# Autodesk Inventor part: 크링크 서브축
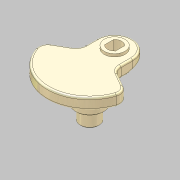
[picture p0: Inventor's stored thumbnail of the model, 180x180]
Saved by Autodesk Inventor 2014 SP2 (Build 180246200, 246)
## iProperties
Manager: KYOUNG IL JANG
Company: 한국ATC센터
Created: 2012-10
Part Number: 크링크 서브축
Document SubType Name: Modeling
Density: 1 g/cm^3
Checked By: KYOUNG IL JANG
Vendor: CBT Solutions
Designer: KYOUNG IL JANG
Material: 일반
Appearance: _시험_금속-티타늄(광택)
Author: KYOUNG IL JANG
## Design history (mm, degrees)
sketch "스케치1"
  geometry: L1 (-19, 109.368)-(-19, 91.368); L2 (-19, 91.368)-(-44.545, 76.619); L3 (19, 109.368)-(19, 91.368); L4 (19, 91.368)-(44.545, 76.619); C1 r 32.5 at (0, 83) reference; C2 r 10 at (0, 83); C3 r 17.5 at (0, 83); A1 r 45 centre (0, 83) between (-44.545, 76.619) and (44.545, 76.619); A2 r 32.5 centre (0, 83) between (-19, 109.368) and (19, 109.368); A3 r 19 centre (0, 109.368) between (19, 109.368) and (-19, 109.368); 1 further point
  constraints: 8 end point, 6 point on circle, 5 centre point, 4 coincident, 2 equal length, 1 horizontal alignment, 1 parallel, 1 tangent, 1 vertical, 1 vertical alignment
  dimensions: "d0" = 20 diameter of C2; "d1" = 35 diameter of C3; "d2" = 90 diameter of A1 (derived); "d3" = 65 diameter of A2 (derived); "d4" = 120 deg angle of L3 L4; "d5" = 19 radius of A3 (derived); "d6" = 18 distance of L1.start L1.end (derived)
  node "참조1"
extrude "돌출1" new body sketch "스케치1" distance "d7" = 12; taper "d8" = 0 deg
extrude "돌출2" join sketch "스케치1" distance "d9" = 5; taper "d10" = 0 deg
extrude "돌출3" join sketch "스케치1" distance "d11" = 41; taper "d12" = 0 deg
sketch "스케치2"
  geometry: C1 r 7.5 at (0, 109.368); C2 r 11 at (0, 109.368); A1 r 19 centre (0, 109.368) between (19, 109.368) and (-19, 109.368) reference; 1 further point
  constraints: 2 centre point, 2 coincident
  dimensions: "d13" = 15 diameter of C1; "d14" = 22 diameter of C2
extrude "돌출4" join sketch "스케치2" distance "d15" = 3; taper "d16" = 0 deg
extrude "돌출6" cut sketch "스케치2" stored distance "d19" = 10; taper "d20" = 0 deg
sketch "스케치3"
  geometry: L1 (-5.75, 4.815)-(-5.75, -4.815); L2 (5.75, 4.815)-(5.75, -4.815); A1 r 7.5 centre (0, 0) between (-5.75, 4.815) and (-5.75, -4.815) reference; 1 further point
  constraints: 4 end point, 4 point on circle, 2 parallel, 1 vertical
  dimensions: "d21" = 11.5 distance between parallel lines of L2 L1
extrude "돌출7" join sketch "스케치3" stored distance "d22" = 10; taper "d23" = 0 deg
sketch "스케치4"
  geometry: C1 r 10 at (0, 0) reference; C2 r 15 at (0, 0); 1 further point
  constraints: 1 centre point, 1 coincident
  dimensions: "d30" = 30 diameter of C2
extrude "돌출8" join sketch "스케치4" distance "d28" = 21; taper "d29" = 0 deg
chamfer "모따기1" distance "d31" = 1; stored, may be unused: second distance "d32" = 2, angle "d33" = 45 deg
sketch "스케치5"
  geometry: L1 (-19, 91.368)-(-19, 109.368) reference; L2 (19, 109.368)-(19, 91.368) reference; C1 r 9 at (0, 83); 3 further points
  constraints: 2 point on line, 1 centre point, 1 horizontal alignment
  dimensions: "d34" = 21 vertical distance of point (-19, 104) C1.centre (derived)
node "작업 평면1"
  node "작업축2"
sketch "스케치6"
  geometry: L1 (0, 50)-(38, 50); L2 (38, 50)-(38, 0); L3 (38, 0)-(0, 0); L4 (0, 0)-(0, 50); L5 (0, -12.202)-(0, 5.185) reference; L6 (38, 5.185)-(38, -12.202) reference; 2 further points
  constraints: 8 end point, 2 collinear, 1 point on line
  dimensions: "d37" = 50 distance from line of L1 L3.end
extrude "돌출9" cut sketch "스케치6" stored distance "d38" = 20.7; taper "d39" = 0 deg
fillet "모깎기1" dims "d26" = 10, "d27" = 2
node "솔리드1"
other parameters: "d35" = -15 deg (derived)
